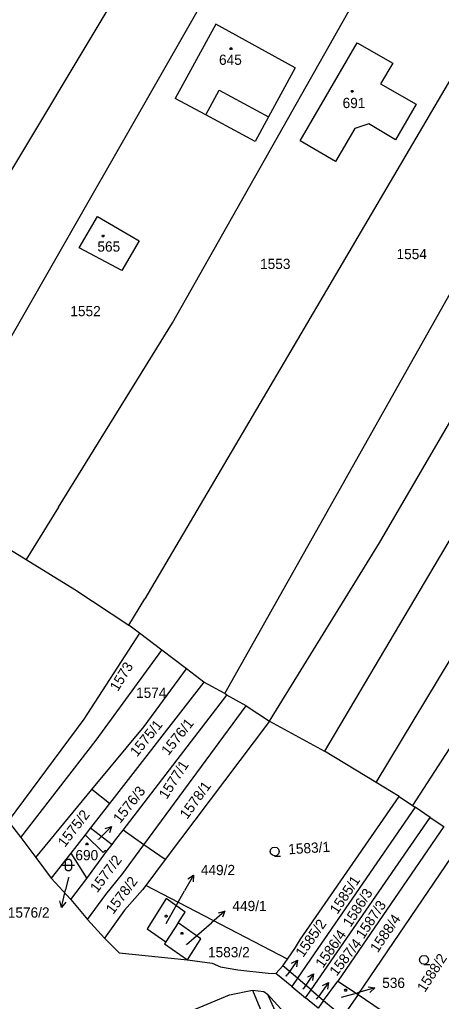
# Model space of a CAD drawing. Extents: x -580630 to -576196, y -1189024 to -1183567.
# Drawn here: x -578816.9 to -578746.6, y -1185522.1 to -1185358.8 of the extents above; entities that cross this region are included whole.
import ezdxf

# ---------------------------------------------------------------- set-up
doc = ezdxf.new("R2010")
doc.units = 0
for name, color, linetype in [('Vrstva 1', 7, 'Continuous'), ('Vrstva 16', 7, 'Continuous'), ('Vrstva 18', 7, 'Continuous'), ('Vrstva 19', 7, 'Continuous'), ('Vrstva 25', 7, 'Continuous'), ('Vrstva 4', 7, 'Continuous')]:
    doc.layers.add(name, color=color, linetype=linetype)

msp = doc.modelspace()

# ---------------------------------------------------------------- linework, layer by layer
at = {"layer": 'Vrstva 1'}
for p, q in [((-578793.76, -1185342.93), (-578862.82, -1185458.11)), ((-578833.3, -1185437.78), (-578781.26, -1185346.84)), ((-578791.42, -1185409.18), (-578758.75, -1185351.47)), ((-578782.68, -1185470.84), (-578717.4, -1185354.98)), ((-578737.6, -1185355.83), (-578771.13, -1185412.9)), ((-578784.19, -1185359.53), (-578790.94, -1185371.9)), ((-578770.96, -1185366.76), (-578784.19, -1185359.53)), ((-578694.5, -1185359.47), (-578766.11, -1185480.47)), ((-578770.13, -1185378.91), (-578760.68, -1185362.65)), ((-578760.68, -1185362.65), (-578754.74, -1185366.03)), ((-578670.57, -1185364.05), (-578751.46, -1185489.49)), ((-578754.74, -1185366.03), (-578756.75, -1185369.47)), ((-578770.96, -1185366.76), (-578775.42, -1185374.93)), ((-578756.75, -1185369.47), (-578750.85, -1185372.84)), ((-578785.86, -1185374.63), (-578790.94, -1185371.9)), ((-578750.85, -1185372.84), (-578754.29, -1185378.76)), ((-578777.67, -1185379.04), (-578785.86, -1185374.63)), ((-578775.42, -1185374.93), (-578777.67, -1185379.04)), ((-578761.03, -1185376.87), (-578764.25, -1185382.36)), ((-578758.71, -1185376.12), (-578761.03, -1185376.87)), ((-578754.29, -1185378.76), (-578758.71, -1185376.12)), ((-578764.25, -1185382.36), (-578770.13, -1185378.91)), ((-578756.92, -1185445.82), (-578721.94, -1185385.62)), ((-578806.95, -1185396.74), (-578803.87, -1185391.5)), ((-578803.87, -1185391.5), (-578796.97, -1185395.55)), ((-578796.97, -1185395.55), (-578799.86, -1185400.47)), ((-578799.86, -1185400.47), (-578806.95, -1185396.74)), ((-578810.38, -1185439.84), (-578791.42, -1185409.18)), ((-578771.13, -1185412.9), (-578796.01, -1185455.11)), ((-578757.5, -1185485.68), (-578727.78, -1185436.28)), ((-578810.38, -1185439.84), (-578815.79, -1185448.55)), ((-578823.19, -1185444), (-578815.79, -1185448.55)), ((-578775.28, -1185475.48), (-578756.92, -1185445.82)), ((-578815.79, -1185448.55), (-578807.67, -1185453.55)), ((-578807.67, -1185453.55), (-578798.67, -1185459.46)), ((-578798.67, -1185459.46), (-578796.01, -1185455.11)), ((-578796.89, -1185460.81), (-578806.19, -1185475.1)), ((-578796.89, -1185460.81), (-578798.67, -1185459.46)), ((-578793.18, -1185463.63), (-578796.89, -1185460.81)), ((-578804.12, -1185478.63), (-578793.18, -1185463.63)), ((-578789.08, -1185466.76), (-578793.18, -1185463.63)), ((-578796.15, -1185476.34), (-578789.08, -1185466.76)), ((-578786.18, -1185468.97), (-578789.08, -1185466.76)), ((-578786.18, -1185468.97), (-578801.88, -1185489.13)), ((-578782.68, -1185470.84), (-578786.18, -1185468.97)), ((-578799.62, -1185493.57), (-578782.37, -1185471.13)), ((-578782.37, -1185471.13), (-578782.68, -1185470.84)), ((-578779.14, -1185472.88), (-578782.37, -1185471.13)), ((-578796.18, -1185496.05), (-578779.14, -1185472.88)), ((-578779.14, -1185472.88), (-578775.28, -1185475.48)), ((-578806.19, -1185475.1), (-578818.74, -1185492.08)), ((-578775.28, -1185475.48), (-578792.62, -1185498.48)), ((-578775.28, -1185475.48), (-578766.11, -1185480.47)), ((-578804.81, -1185486.81), (-578796.15, -1185476.34)), ((-578816.67, -1185494.83), (-578804.12, -1185478.63)), ((-578757.5, -1185485.68), (-578766.11, -1185480.47)), ((-578814.18, -1185498.14), (-578804.81, -1185486.81)), ((-578801.88, -1185489.13), (-578804.81, -1185486.81)), ((-578753.66, -1185488.01), (-578757.5, -1185485.68)), ((-578770.1, -1185511.72), (-578753.66, -1185488.01)), ((-578753.66, -1185488.01), (-578751.46, -1185489.49)), ((-578801.88, -1185489.13), (-578805.06, -1185493.21)), ((-578751.03, -1185489.78), (-578768.41, -1185515.05)), ((-578751.46, -1185489.49), (-578751.03, -1185489.78)), ((-578748.51, -1185491.47), (-578751.03, -1185489.78)), ((-578766.08, -1185516.9), (-578748.51, -1185491.47)), ((-578748.51, -1185491.47), (-578746.25, -1185492.99)), ((-578818.74, -1185492.08), (-578816.67, -1185494.83)), ((-578805.06, -1185493.21), (-578805.94, -1185494.34)), ((-578805.06, -1185493.21), (-578801.45, -1185495.95)), ((-578746.25, -1185492.99), (-578763.89, -1185518.7)), ((-578816.67, -1185494.83), (-578814.18, -1185498.14)), ((-578805.94, -1185494.34), (-578808.33, -1185497.4)), ((-578802.93, -1185497.29), (-578805.94, -1185494.34)), ((-578800.89, -1185495.22), (-578799.62, -1185493.57)), ((-578796.18, -1185496.05), (-578799.62, -1185493.57)), ((-578760.47, -1185520.91), (-578742.96, -1185495.14)), ((-578802.37, -1185497.14), (-578801.45, -1185495.95)), ((-578801.45, -1185495.95), (-578800.89, -1185495.22)), ((-578797.57, -1185497.93), (-578796.18, -1185496.05)), ((-578792.62, -1185498.48), (-578796.18, -1185496.05)), ((-578814.18, -1185498.14), (-578811.59, -1185501.58)), ((-578808.33, -1185497.4), (-578811.59, -1185501.58)), ((-578808.33, -1185497.4), (-578805.66, -1185501.6)), ((-578805.66, -1185501.6), (-578802.37, -1185497.14)), ((-578802.62, -1185496.99), (-578802.93, -1185497.29)), ((-578802.37, -1185497.14), (-578802.62, -1185496.99)), ((-578799.65, -1185500.77), (-578797.57, -1185497.93)), ((-578792.62, -1185498.48), (-578795.87, -1185502.79)), ((-578811.59, -1185501.58), (-578808.33, -1185505.09)), ((-578808.33, -1185505.09), (-578805.66, -1185501.6)), ((-578802.5, -1185504.29), (-578799.65, -1185500.77)), ((-578795.87, -1185502.79), (-578796.4, -1185503.49)), ((-578772.28, -1185515.02), (-578795.87, -1185502.79)), ((-578805.58, -1185508.42), (-578802.5, -1185504.29)), ((-578796.4, -1185503.49), (-578799.41, -1185506.87)), ((-578792.46, -1185504.96), (-578795.65, -1185509.97)), ((-578789.28, -1185507.2), (-578792.46, -1185504.96)), ((-578808.33, -1185505.09), (-578805.58, -1185508.42)), ((-578799.41, -1185506.87), (-578802.73, -1185511.57)), ((-578790.46, -1185509.01), (-578789.28, -1185507.2)), ((-578802.73, -1185511.57), (-578805.58, -1185508.42)), ((-578790.46, -1185509.01), (-578792.53, -1185512.18)), ((-578786.7, -1185511.64), (-578790.46, -1185509.01)), ((-578795.65, -1185509.97), (-578792.53, -1185512.18)), ((-578802.73, -1185511.57), (-578800.26, -1185513.98)), ((-578792.53, -1185512.18), (-578792.73, -1185512.5)), ((-578792.73, -1185512.5), (-578788.89, -1185515.13)), ((-578788.89, -1185515.13), (-578787.21, -1185512.44)), ((-578787.21, -1185512.44), (-578786.7, -1185511.64)), ((-578772.28, -1185515.02), (-578770.94, -1185513.09)), ((-578770.94, -1185513.09), (-578770.1, -1185511.72)), ((-578800.26, -1185513.98), (-578788.89, -1185515.13)), ((-578788.89, -1185515.13), (-578784.83, -1185515.71)), ((-578784.83, -1185515.71), (-578783.43, -1185516.31)), ((-578783.43, -1185516.31), (-578780.53, -1185516.8)), ((-578774.18, -1185517.43), (-578773.06, -1185516.15)), ((-578773.06, -1185516.15), (-578772.28, -1185515.02)), ((-578770.59, -1185518.22), (-578773.06, -1185516.15)), ((-578768.41, -1185515.05), (-578770.59, -1185518.22)), ((-578780.53, -1185516.8), (-578775.47, -1185517.39)), ((-578775.47, -1185517.39), (-578774.18, -1185517.43)), ((-578771.54, -1185519.6), (-578774.18, -1185517.43)), ((-578768.33, -1185520.15), (-578766.08, -1185516.9)), ((-578770.59, -1185518.22), (-578771.54, -1185519.6)), ((-578771.54, -1185519.6), (-578769.25, -1185521.47)), ((-578769.7, -1185518.97), (-578770.59, -1185518.22)), ((-578768.33, -1185520.15), (-578769.7, -1185518.97)), ((-578766.25, -1185521.92), (-578763.89, -1185518.7)), ((-578763.89, -1185518.7), (-578760.47, -1185520.91)), ((-578790.69, -1185524.65), (-578781.89, -1185520.97)), ((-578781.89, -1185520.97), (-578778.1, -1185520.19)), ((-578778.1, -1185520.19), (-578771.19, -1185536.6)), ((-578778.1, -1185520.19), (-578776.18, -1185520.44)), ((-578776.18, -1185520.44), (-578775.57, -1185520.89)), ((-578775.57, -1185520.89), (-578769, -1185535.61)), ((-578764.22, -1185533.34), (-578775.57, -1185520.89)), ((-578769.25, -1185521.47), (-578768.33, -1185520.15)), ((-578768.33, -1185520.15), (-578766.25, -1185521.92)), ((-578760.47, -1185520.91), (-578763.06, -1185524.59)), ((-578760.47, -1185520.91), (-578756.67, -1185523.51)), ((-578767.17, -1185523.17), (-578769.25, -1185521.47)), ((-578766.25, -1185521.92), (-578767.17, -1185523.17)), ((-578766.25, -1185521.92), (-578763.06, -1185524.59))]:
    msp.add_line(p, q, dxfattribs=at)
at = {"layer": 'Vrstva 16'}
for p, q in [((-578801.579, -1185492.949), (-578803.67, -1185495.1)), ((-578803.71, -1185495.14), (-578803.67, -1185495.1)), ((-578808.74, -1185501.48), (-578809.21, -1185503.51)), ((-578787.917, -1185501.056), (-578789.39, -1185503.67)), ((-578809.884, -1185506.433), (-578809.21, -1185503.51)), ((-578792.46, -1185509.11), (-578789.39, -1185503.67)), ((-578782.668, -1185507.04), (-578784.93, -1185509.01)), ((-578789.06, -1185512.61), (-578784.93, -1185509.01)), ((-578770.606, -1185515.191), (-578772.31, -1185517.66)), ((-578772.46, -1185517.87), (-578772.31, -1185517.66)), ((-578767.926, -1185517.458), (-578769.61, -1185519.94)), ((-578765.456, -1185518.915), (-578767.18, -1185521.37)), ((-578769.68, -1185520.04), (-578769.61, -1185519.94)), ((-578763.29, -1185521.38), (-578760.62, -1185520.64)), ((-578757.73, -1185519.835), (-578760.62, -1185520.64)), ((-578767.41, -1185521.69), (-578767.18, -1185521.37))]:
    msp.add_line(p, q, dxfattribs=at)
for points in [[(-578802.635, -1185493.317), (-578801.579, -1185492.949), (-578801.917, -1185494.014)], [(-578788.844, -1185501.682), (-578787.917, -1185501.056), (-578787.972, -1185502.173)], [(-578809.172, -1185505.571), (-578809.884, -1185506.433), (-578810.147, -1185505.347)], [(-578783.75, -1185507.319), (-578782.668, -1185507.04), (-578783.094, -1185508.073)], [(-578771.585, -1185515.73), (-578770.606, -1185515.191), (-578770.762, -1185516.298)], [(-578768.901, -1185518.004), (-578767.926, -1185517.458), (-578768.073, -1185518.566)], [(-578766.44, -1185519.446), (-578765.456, -1185518.915), (-578765.621, -1185520.021)], [(-578758.827, -1185519.622), (-578757.73, -1185519.835), (-578758.559, -1185520.585)]]:
    msp.add_lwpolyline(points, dxfattribs=at)
at = {"layer": 'Vrstva 25'}
for points in [[(-578781.57, -1185363.44), (-578781.48, -1185363.59), (-578781.57, -1185363.74), (-578781.75, -1185363.74), (-578781.84, -1185363.59), (-578781.75, -1185363.44)], [(-578761.39, -1185370.55), (-578761.3, -1185370.7), (-578761.39, -1185370.85), (-578761.57, -1185370.85), (-578761.66, -1185370.7), (-578761.57, -1185370.55)], [(-578802.87, -1185394.61), (-578802.78, -1185394.76), (-578802.87, -1185394.91), (-578803.05, -1185394.91), (-578803.14, -1185394.76), (-578803.05, -1185394.61)], [(-578805.55, -1185495.72), (-578805.46, -1185495.87), (-578805.55, -1185496.02), (-578805.73, -1185496.02), (-578805.82, -1185495.87), (-578805.73, -1185495.72)], [(-578809.24, -1185498.88), (-578809.14, -1185498.59), (-578808.89, -1185498.41), (-578808.58, -1185498.41), (-578808.33, -1185498.59), (-578808.23, -1185498.88), (-578808.23, -1185499.88), (-578808.33, -1185500.17), (-578808.58, -1185500.35), (-578808.89, -1185500.35), (-578809.14, -1185500.17), (-578809.24, -1185499.88)], [(-578792.37, -1185507.75), (-578792.28, -1185507.9), (-578792.37, -1185508.05), (-578792.55, -1185508.05), (-578792.64, -1185507.9), (-578792.55, -1185507.75)], [(-578789.74, -1185510.58), (-578789.65, -1185510.73), (-578789.74, -1185510.88), (-578789.92, -1185510.88), (-578790.01, -1185510.73), (-578789.92, -1185510.58)], [(-578762.49, -1185520.04), (-578762.4, -1185520.19), (-578762.49, -1185520.34), (-578762.67, -1185520.34), (-578762.76, -1185520.19), (-578762.67, -1185520.04)]]:
    msp.add_lwpolyline(points, close=True, dxfattribs=at)
for points in [[(-578774.38, -1185497.87), (-578774.76, -1185497.77), (-578775.03, -1185497.5), (-578775.13, -1185497.13), (-578775.03, -1185496.76), (-578774.76, -1185496.49), (-578774.39, -1185496.39), (-578774.02, -1185496.49), (-578773.75, -1185496.76), (-578773.65, -1185497.14), (-578773.75, -1185497.52), (-578774.02, -1185497.79), (-578774.4, -1185497.89), (-578773.4, -1185497.89)], [(-578809.74, -1185499.38), (-578808.47, -1185499.38), (-578807.74, -1185499.38)], [(-578749.52, -1185515.89), (-578749.9, -1185515.79), (-578750.17, -1185515.52), (-578750.27, -1185515.15), (-578750.17, -1185514.78), (-578749.9, -1185514.51), (-578749.53, -1185514.41), (-578749.16, -1185514.51), (-578748.89, -1185514.78), (-578748.79, -1185515.16), (-578748.89, -1185515.54), (-578749.16, -1185515.81), (-578749.54, -1185515.91), (-578748.54, -1185515.91)]]:
    msp.add_lwpolyline(points, dxfattribs=at)
at = {"layer": 'Vrstva 4'}
for p, q in [((-578785.86, -1185374.63), (-578783.62, -1185370.49)), ((-578783.62, -1185370.49), (-578775.42, -1185374.93))]:
    msp.add_line(p, q, dxfattribs=at)

# ---------------------------------------------------------------- texts
at = {"layer": 'Vrstva 16'}
for s, rotation, p in [('1576/3', 51.68079, (-578800.117, -1185492.572)), ('1585/2', 55.11854, (-578769.665, -1185514.868)), ('1586/4', 55.17584, (-578766.366, -1185516.628)), ('1587/4', 52.25375, (-578764.08, -1185517.979))]:
    msp.add_text(s, height=1.7, rotation=rotation, dxfattribs=at).set_placement(p)
for s, p in [('449/2', (-578786.683, -1185501.06)), ('1576/2', (-578818.828, -1185508.13)), ('449/1', (-578781.433, -1185507.04)), ('536', (-578756.493, -1185519.83))]:
    msp.add_text(s, height=1.7, dxfattribs=at).set_placement(p)
at = {"layer": 'Vrstva 18'}
for s, height, p in [('1554', 1.7, (-578754.109, -1185398.61)), ('1553', 1.7, (-578776.826, -1185400.25)), ('1552', 1.7, (-578808.413, -1185408.1)), ('1574', 1.7, (-578797.472, -1185471.58)), ('1576/3', 0.1, (-578803.938, -1185495.14)), ('1576/2', 0.1, (-578808.967, -1185501.48)), ('1583/2', 1.7, (-578785.499, -1185514.73)), ('1585/2', 0.1, (-578772.693, -1185517.87)), ('1586/4', 0.1, (-578769.906, -1185520.04))]:
    msp.add_text(s, height=height, dxfattribs=at).set_placement(p)
for s, height, rotation, p in [('1573', 1.7, 58.84277, (-578800.496, -1185470.625)), ('1575/1', 1.7, 51.10784, (-578797.315, -1185481.509)), ('1576/1', 1.7, 51.39431, (-578792.102, -1185481.293)), ('1577/1', 1.7, 57.35308, (-578792.37, -1185488.567)), ('1578/1', 1.7, 54.2591, (-578788.961, -1185491.878)), ('1575/2', 1.7, 52.36834, (-578809.332, -1185496.55)), ('1583/1', 1.7, 3.49504, (-578772.08, -1185497.609)), ('1577/2', 1.7, 52.88401, (-578803.932, -1185504.102)), ('1578/2', 1.7, 53.17048, (-578801.277, -1185507.677)), ('1585/1', 1.7, 56.03527, (-578763.962, -1185507.682)), ('1586/3', 1.7, 57.23848, (-578761.759, -1185509.839)), ('1587/3', 1.7, 56.32175, (-578759.6, -1185511.791)), ('1588/4', 1.7, 55.80609, (-578757.238, -1185514.075)), ('1588/2', 1.7, 57.29578, (-578749.383, -1185520.673)), ('1587/4', 0.1, 22.45994, (-578767.617, -1185521.776))]:
    msp.add_text(s, height=height, rotation=rotation, dxfattribs=at).set_placement(p)
at = {"layer": 'Vrstva 19'}
for s, height, p in [('645', 1.7, (-578783.661, -1185366.29)), ('691', 1.7, (-578763.086, -1185373.48)), ('565', 1.7, (-578803.908, -1185397.36)), ('690', 1.7, (-578807.571, -1185498.59)), ('449/2', 0.1, (-578792.666, -1185509)), ('449/1', 0.1, (-578789.241, -1185512.61)), ('536', 0.1, (-578763.413, -1185521.38))]:
    msp.add_text(s, height=height, dxfattribs=at).set_placement(p)

doc.saveas('drawing.dxf')
